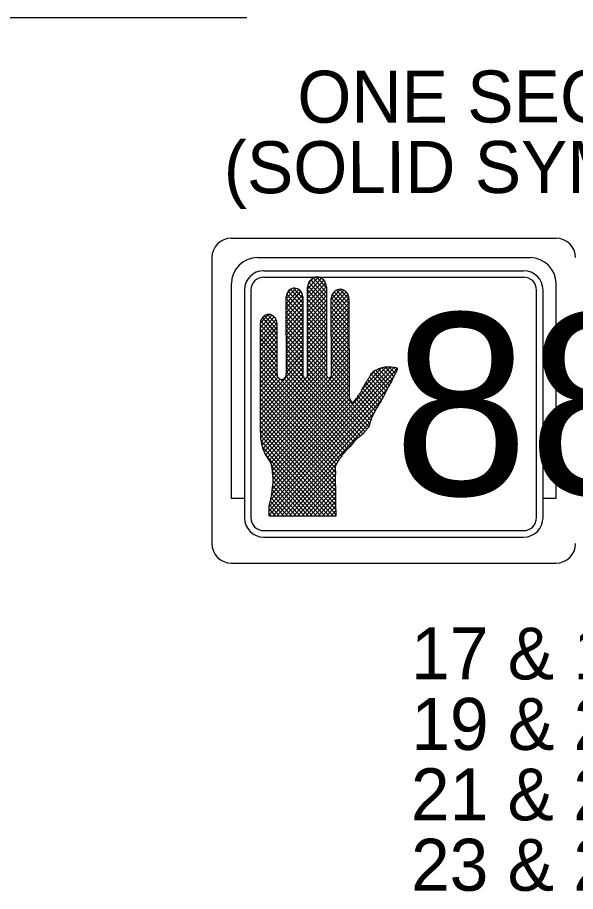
# Model space of a CAD drawing. Extents: x -19.5 to 29.5, y 0.4 to 10.6.
# Drawn here: x 4.931 to 5.647, y 9.087 to 10.208 of the extents above; entities that cross this region are included whole.
import ezdxf

# ---------------------------------------------------------------- set-up
doc = ezdxf.new("R2010")
doc.units = 0
doc.layers.add('T_Drafting', color=7, linetype='Continuous')
doc.layers.add('T_Notes', color=7, linetype='Continuous')

msp = doc.modelspace()

# ---------------------------------------------------------------- linework, layer by layer
at = {"layer": 'T_Drafting'}
for p, q in [((5.205, 9.9248), (5.6217, 9.9248)), ((5.18, 9.8998), (5.18, 9.5331)), ((5.2384, 9.8998), (5.5884, 9.8998)), ((5.2467, 9.8831), (5.58, 9.8831)), ((5.2467, 9.8748), (5.58, 9.8748)), ((5.3028, 9.8595), (5.3165, 9.8748)), ((5.3146, 9.8748), (5.3271, 9.8609)), ((5.205, 9.8665), (5.205, 9.5915)), ((5.3028, 9.8536), (5.3205, 9.8734)), ((5.3028, 9.8478), (5.3236, 9.8709)), ((5.3028, 9.8419), (5.3258, 9.8675)), ((5.3028, 9.836), (5.3271, 9.863)), ((5.303, 9.8641), (5.3272, 9.8373)), ((5.3037, 9.8664), (5.3103, 9.8738)), ((5.3045, 9.8683), (5.3272, 9.8432)), ((5.3069, 9.8715), (5.3272, 9.8491)), ((5.3102, 9.8738), (5.3272, 9.855)), ((5.3223, 9.8721), (5.3247, 9.8695)), ((5.6217, 9.5915), (5.6217, 9.8665)), ((5.2217, 9.8581), (5.2217, 9.5665)), ((5.23, 9.8581), (5.23, 9.5665)), ((5.2755, 9.8469), (5.2877, 9.8605)), ((5.2755, 9.841), (5.2916, 9.8589)), ((5.2755, 9.8351), (5.2944, 9.8562)), ((5.2755, 9.8292), (5.2962, 9.8523)), ((5.276, 9.8528), (5.2967, 9.8299)), ((5.2764, 9.8538), (5.2816, 9.8596)), ((5.278, 9.8566), (5.2967, 9.8358)), ((5.2809, 9.8592), (5.2967, 9.8417)), ((5.2849, 9.8606), (5.2967, 9.8476)), ((5.292, 9.8586), (5.2948, 9.8555)), ((5.3029, 9.7481), (5.3028, 9.8619)), ((5.3028, 9.8585), (5.3272, 9.8314)), ((5.3028, 9.8301), (5.3272, 9.8572)), ((5.3028, 9.8526), (5.3272, 9.8255)), ((5.3271, 9.8622), (5.3273, 9.7493)), ((5.3333, 9.8463), (5.345, 9.8594)), ((5.3333, 9.8404), (5.3493, 9.8582)), ((5.3333, 9.8345), (5.3525, 9.8558)), ((5.3333, 9.8286), (5.3547, 9.8525)), ((5.3345, 9.8527), (5.356, 9.8288)), ((5.3368, 9.856), (5.356, 9.8347)), ((5.34, 9.8583), (5.356, 9.8406)), ((5.3444, 9.8594), (5.3559, 9.8465)), ((5.5967, 9.5665), (5.5967, 9.8581)), ((5.605, 9.5665), (5.605, 9.8581)), ((5.2756, 9.7503), (5.2755, 9.8497)), ((5.2755, 9.8476), (5.2967, 9.824)), ((5.2755, 9.8233), (5.2967, 9.8469)), ((5.2755, 9.8417), (5.2967, 9.8181)), ((5.2755, 9.8174), (5.2967, 9.841)), ((5.2967, 9.8494), (5.2968, 9.7487)), ((5.3028, 9.8242), (5.3272, 9.8513)), ((5.3028, 9.8467), (5.3272, 9.8196)), ((5.3028, 9.8183), (5.3272, 9.8454)), ((5.3028, 9.8408), (5.3272, 9.8137)), ((5.3333, 9.8482), (5.356, 9.8229)), ((5.3334, 9.7487), (5.3333, 9.8479)), ((5.3333, 9.8227), (5.3559, 9.8479)), ((5.3333, 9.8423), (5.356, 9.817)), ((5.3333, 9.8169), (5.356, 9.842)), ((5.3559, 9.8471), (5.3561, 9.7194)), ((5.2755, 9.8358), (5.2967, 9.8122)), ((5.2755, 9.8116), (5.2967, 9.8351)), ((5.2755, 9.8299), (5.2967, 9.8063)), ((5.2755, 9.8057), (5.2967, 9.8292)), ((5.3028, 9.8125), (5.3272, 9.8395)), ((5.3028, 9.8349), (5.3272, 9.8078)), ((5.3028, 9.8066), (5.3272, 9.8336)), ((5.3333, 9.8364), (5.356, 9.8111)), ((5.3333, 9.811), (5.356, 9.8361)), ((5.3333, 9.8305), (5.356, 9.8052)), ((5.3333, 9.8051), (5.356, 9.8303)), ((5.2423, 9.8159), (5.2522, 9.827)), ((5.2423, 9.8101), (5.2568, 9.8262)), ((5.2423, 9.8042), (5.2601, 9.8239)), ((5.2423, 9.7983), (5.2624, 9.8206)), ((5.2429, 9.819), (5.2636, 9.796)), ((5.2448, 9.8228), (5.2636, 9.8019)), ((5.2477, 9.8254), (5.2635, 9.8078)), ((5.2516, 9.8269), (5.2635, 9.8137)), ((5.2584, 9.8253), (5.2621, 9.8212)), ((5.2755, 9.824), (5.2967, 9.8004)), ((5.2755, 9.7998), (5.2967, 9.8233)), ((5.2755, 9.8181), (5.2967, 9.7945)), ((5.3028, 9.829), (5.3272, 9.8019)), ((5.3028, 9.8007), (5.3272, 9.8277)), ((5.3028, 9.8231), (5.3272, 9.796)), ((5.3028, 9.7948), (5.3272, 9.8219)), ((5.3333, 9.8246), (5.356, 9.7994)), ((5.3333, 9.7992), (5.356, 9.8244)), ((5.3333, 9.8187), (5.356, 9.7935)), ((5.3333, 9.7933), (5.356, 9.8185)), ((5.2425, 9.6786), (5.2423, 9.816)), ((5.2423, 9.7924), (5.2635, 9.8159)), ((5.2423, 9.8137), (5.2636, 9.7901)), ((5.2423, 9.8078), (5.2636, 9.7842)), ((5.2424, 9.7865), (5.2635, 9.8101)), ((5.2635, 9.8158), (5.2636, 9.7502)), ((5.2755, 9.7939), (5.2967, 9.8175)), ((5.2755, 9.8122), (5.2967, 9.7886)), ((5.2755, 9.788), (5.2967, 9.8116)), ((5.3028, 9.8172), (5.3272, 9.7901)), ((5.3028, 9.7889), (5.3272, 9.816)), ((5.3028, 9.8113), (5.3272, 9.7842)), ((5.3028, 9.783), (5.3272, 9.8101)), ((5.3333, 9.8128), (5.356, 9.7876)), ((5.3333, 9.7874), (5.356, 9.8126)), ((5.3333, 9.8069), (5.356, 9.7817)), ((5.3333, 9.7816), (5.356, 9.8067)), ((5.2423, 9.8019), (5.2636, 9.7783)), ((5.2423, 9.796), (5.2636, 9.7724)), ((5.2424, 9.7806), (5.2636, 9.8042)), ((5.2424, 9.7748), (5.2636, 9.7983)), ((5.2755, 9.8063), (5.2967, 9.7827)), ((5.2755, 9.7821), (5.2967, 9.8057)), ((5.2755, 9.8004), (5.2968, 9.7768)), ((5.2755, 9.7763), (5.2967, 9.7998)), ((5.3028, 9.8054), (5.3272, 9.7783)), ((5.3028, 9.7995), (5.3272, 9.7724)), ((5.3029, 9.7771), (5.3272, 9.8042)), ((5.3029, 9.7713), (5.3272, 9.7983)), ((5.3333, 9.801), (5.356, 9.7758)), ((5.3333, 9.7757), (5.356, 9.8008)), ((5.2423, 9.7901), (5.2636, 9.7665)), ((5.2424, 9.7689), (5.2636, 9.7924)), ((5.2424, 9.763), (5.2636, 9.7865)), ((5.2755, 9.7945), (5.2968, 9.7709)), ((5.2755, 9.7704), (5.2967, 9.7939)), ((5.2755, 9.7886), (5.2968, 9.765)), ((5.2755, 9.7645), (5.2967, 9.788)), ((5.3028, 9.7936), (5.3273, 9.7665)), ((5.3028, 9.7877), (5.3273, 9.7606)), ((5.3029, 9.7654), (5.3272, 9.7924)), ((5.3029, 9.7595), (5.3272, 9.7866)), ((5.3333, 9.7951), (5.356, 9.7699)), ((5.3333, 9.7698), (5.356, 9.7949)), ((5.3333, 9.7892), (5.356, 9.764)), ((5.3334, 9.7639), (5.356, 9.7891)), ((5.2424, 9.7842), (5.2636, 9.7606)), ((5.2424, 9.7571), (5.2636, 9.7806)), ((5.2424, 9.7783), (5.2636, 9.7547)), ((5.2424, 9.7512), (5.2636, 9.7748)), ((5.2755, 9.7827), (5.2968, 9.7591)), ((5.2755, 9.7768), (5.2968, 9.7532)), ((5.2756, 9.7586), (5.2967, 9.7821)), ((5.2756, 9.7527), (5.2968, 9.7763)), ((5.3028, 9.7818), (5.3273, 9.7547)), ((5.3028, 9.7476), (5.3272, 9.7748)), ((5.3029, 9.7536), (5.3272, 9.7807)), ((5.3029, 9.7759), (5.3272, 9.7489)), ((5.3333, 9.7833), (5.356, 9.7581)), ((5.3333, 9.7774), (5.356, 9.7522)), ((5.3334, 9.758), (5.356, 9.7832)), ((5.3334, 9.7521), (5.356, 9.7773)), ((5.2424, 9.7724), (5.2638, 9.7486)), ((5.2424, 9.71), (5.2968, 9.7704)), ((5.2424, 9.7453), (5.2636, 9.7689)), ((5.2424, 9.7665), (5.3487, 9.6484)), ((5.2424, 9.7041), (5.2968, 9.7645)), ((5.2424, 9.7394), (5.2636, 9.763)), ((5.2427, 9.6749), (5.3273, 9.7689)), ((5.2429, 9.6692), (5.3273, 9.763)), ((5.2473, 9.6507), (5.356, 9.7714)), ((5.2494, 9.647), (5.356, 9.7655)), ((5.2755, 9.7709), (5.297, 9.747)), ((5.2755, 9.765), (5.3647, 9.666)), ((5.3029, 9.77), (5.3811, 9.6831)), ((5.3029, 9.7641), (5.3788, 9.6798)), ((5.3333, 9.7715), (5.356, 9.7463)), ((5.3334, 9.7656), (5.3561, 9.7404)), ((5.2424, 9.7606), (5.3462, 9.6452)), ((5.2424, 9.6982), (5.2968, 9.7586)), ((5.2424, 9.7336), (5.2636, 9.7571)), ((5.2424, 9.7547), (5.344, 9.6418)), ((5.2424, 9.7277), (5.2636, 9.7512)), ((5.2425, 9.6924), (5.2968, 9.7527)), ((5.2437, 9.6642), (5.3273, 9.7571)), ((5.2445, 9.6593), (5.3273, 9.7512)), ((5.2515, 9.6435), (5.356, 9.7596)), ((5.2536, 9.6399), (5.356, 9.7537)), ((5.2537, 9.5753), (5.4178, 9.7576)), ((5.2539, 9.5813), (5.414, 9.7592)), ((5.2557, 9.5892), (5.4092, 9.7597)), ((5.2568, 9.5964), (5.4039, 9.7597)), ((5.2756, 9.7591), (5.362, 9.663)), ((5.2756, 9.7532), (5.3594, 9.66)), ((5.3029, 9.7582), (5.3763, 9.6767)), ((5.3029, 9.7523), (5.3737, 9.6737)), ((5.3334, 9.7597), (5.3561, 9.7345)), ((5.3334, 9.7538), (5.3561, 9.7286)), ((5.3734, 9.7318), (5.3976, 9.7587)), ((5.3834, 9.7488), (5.3891, 9.7551)), ((5.3868, 9.7533), (5.4054, 9.7326)), ((5.3901, 9.7555), (5.4075, 9.7362)), ((5.3939, 9.7573), (5.4096, 9.7398)), ((5.3978, 9.7588), (5.4117, 9.7434)), ((5.4022, 9.7597), (5.4133, 9.7474)), ((5.4075, 9.7598), (5.4152, 9.7512)), ((5.4132, 9.7593), (5.4171, 9.755)), ((5.2424, 9.7488), (5.3416, 9.6386)), ((5.2424, 9.7218), (5.2647, 9.7465)), ((5.2424, 9.7159), (5.2677, 9.744)), ((5.2424, 9.7429), (5.3397, 9.6348)), ((5.2425, 9.6865), (5.297, 9.7471)), ((5.2425, 9.6806), (5.3005, 9.7451)), ((5.2456, 9.6546), (5.3282, 9.7464)), ((5.2537, 9.5694), (5.4127, 9.746)), ((5.2556, 9.6362), (5.356, 9.7479)), ((5.2571, 9.6321), (5.3561, 9.742)), ((5.2681, 9.7438), (5.3513, 9.6513)), ((5.2727, 9.7446), (5.354, 9.6542)), ((5.2751, 9.7478), (5.3567, 9.6571)), ((5.2986, 9.7453), (5.3675, 9.6687)), ((5.3025, 9.7468), (5.3706, 9.6711)), ((5.3302, 9.7456), (5.3827, 9.6872)), ((5.3333, 9.748), (5.3561, 9.7227)), ((5.3778, 9.7398), (5.3978, 9.7176)), ((5.3801, 9.7431), (5.3998, 9.7213)), ((5.3821, 9.7467), (5.4017, 9.725)), ((5.3843, 9.7502), (5.4036, 9.7288)), ((5.2424, 9.737), (5.3383, 9.6304)), ((5.2424, 9.7311), (5.3385, 9.6243)), ((5.2577, 9.6268), (5.3561, 9.7361)), ((5.2582, 9.5684), (5.4048, 9.7313)), ((5.2582, 9.6215), (5.3561, 9.7302)), ((5.372, 9.7286), (5.3914, 9.707)), ((5.3737, 9.7325), (5.3936, 9.7104)), ((5.3757, 9.7362), (5.3957, 9.7139)), ((5.2424, 9.7252), (5.3383, 9.6187)), ((5.2424, 9.7193), (5.3383, 9.6128)), ((5.2585, 9.61), (5.3568, 9.7193)), ((5.2586, 9.616), (5.3561, 9.7243)), ((5.2635, 9.5684), (5.3978, 9.7177)), ((5.365, 9.7187), (5.3856, 9.6958)), ((5.3674, 9.7218), (5.3874, 9.6997)), ((5.3697, 9.7252), (5.3894, 9.7033)), ((5.2424, 9.7134), (5.3385, 9.6066)), ((5.2424, 9.7075), (5.3386, 9.6007)), ((5.2576, 9.6031), (5.3588, 9.7155)), ((5.3625, 9.7155), (5.384, 9.6916)), ((5.2424, 9.7016), (5.3386, 9.5948)), ((5.2424, 9.6957), (5.3386, 9.5889)), ((5.2688, 9.5684), (5.3881, 9.701)), ((5.2425, 9.6898), (5.3386, 9.583)), ((5.2425, 9.6839), (5.3389, 9.5768)), ((5.2741, 9.5684), (5.3834, 9.6899)), ((5.2425, 9.678), (5.3392, 9.5705)), ((5.2427, 9.6718), (5.3357, 9.5685)), ((5.2435, 9.665), (5.3304, 9.5685)), ((5.2447, 9.6578), (5.3251, 9.5685)), ((5.2499, 9.6461), (5.3198, 9.5685)), ((5.2571, 9.6323), (5.3145, 9.5685)), ((5.2794, 9.5684), (5.3406, 9.6364)), ((5.2847, 9.5684), (5.3384, 9.6281)), ((5.2579, 9.6255), (5.3092, 9.5685)), ((5.2584, 9.6191), (5.3039, 9.5684)), ((5.29, 9.5684), (5.3384, 9.6222)), ((5.2953, 9.5684), (5.3382, 9.6161)), ((5.2583, 9.6074), (5.2934, 9.5684)), ((5.2586, 9.6129), (5.2987, 9.5684)), ((5.3006, 9.5684), (5.3384, 9.6104)), ((5.2569, 9.5971), (5.2828, 9.5684)), ((5.2575, 9.6024), (5.2881, 9.5684)), ((5.3059, 9.5684), (5.3386, 9.6047)), ((5.3113, 9.5685), (5.3386, 9.5988)), ((5.205, 9.5915), (5.2217, 9.5915)), ((5.254, 9.5827), (5.2669, 9.5684)), ((5.2551, 9.5874), (5.2722, 9.5684)), ((5.2563, 9.5919), (5.2775, 9.5684)), ((5.3166, 9.5685), (5.3386, 9.5929)), ((5.3219, 9.5685), (5.3386, 9.587)), ((5.605, 9.5915), (5.6217, 9.5915)), ((5.2538, 9.5771), (5.2616, 9.5684)), ((5.3272, 9.5685), (5.3387, 9.5812)), ((5.3325, 9.5685), (5.3389, 9.5756)), ((5.2537, 9.5712), (5.2563, 9.5684)), ((5.2542, 9.5684), (5.2537, 9.5689)), ((5.3388, 9.5685), (5.2542, 9.5684)), ((5.3378, 9.5685), (5.3392, 9.57)), ((5.3392, 9.5684), (5.3388, 9.5685)), ((5.2467, 9.5498), (5.58, 9.5498)), ((5.2467, 9.5415), (5.58, 9.5415)), ((5.205, 9.5081), (5.6217, 9.5081))]:
    msp.add_line(p, q, dxfattribs=at)
for centre, radius, start, end in [((5.205, 9.8998), 0.025, 90, 180), ((5.6217, 9.8998), 0.025, 0, 90), ((5.2384, 9.8665), 0.0333, 90, 180), ((5.5884, 9.8665), 0.0333, 0, 90), ((5.2467, 9.8581), 0.025, 90, 180), ((5.2467, 9.8581), 0.0167, 90, 180), ((5.58, 9.8581), 0.025, 0, 90), ((5.58, 9.8581), 0.0167, 0, 90), ((5.2467, 9.5665), 0.025, 180, 270), ((5.2467, 9.5665), 0.0167, 180, 270), ((5.58, 9.5665), 0.025, 270, 0), ((5.58, 9.5665), 0.0167, 270, 0), ((5.205, 9.5331), 0.025, 180, 270), ((5.6217, 9.5331), 0.025, 270, 0)]:
    msp.add_arc(centre, radius, start, end, dxfattribs=at)
for centre, major_axis, start_param, end_param in [((5.315, 9.8613), (0, -0.0136), 1.640121, 4.665593), ((5.2861, 9.8489), (0, -0.0118), 1.618611, 4.644084), ((5.3446, 9.8467), (0, -0.0126), 1.597842, 4.623315), ((5.2529, 9.8152), (0, -0.0118), 1.618611, 4.644084), ((5.2696, 9.7502), (0, -0.00664), 4.713646, 7.855239), ((5.2998, 9.7484), (0, -0.0034), 4.633755, 7.775348), ((5.3303, 9.749), (0, -0.00345), 4.624552, 7.766145)]:
    msp.add_ellipse(centre, major_axis=major_axis, ratio=0.9, start_param=start_param, end_param=end_param, dxfattribs=at)
for points in [[(5.3561, 9.7195), (5.3569, 9.7192), (5.3581, 9.7167), (5.3596, 9.7147), (5.3604, 9.7144), (5.3619, 9.7147), (5.3628, 9.716), (5.3654, 9.7192), (5.3675, 9.7219), (5.3686, 9.7238), (5.3698, 9.7255), (5.3719, 9.7284), (5.373, 9.731), (5.3748, 9.7346), (5.376, 9.7365), (5.378, 9.7401), (5.3803, 9.7434), (5.3821, 9.7467), (5.3841, 9.7499), (5.3859, 9.7522), (5.3885, 9.7548), (5.3917, 9.7561), (5.3935, 9.7571), (5.3962, 9.7581), (5.3985, 9.7591), (5.402, 9.7597), (5.405, 9.7598), (5.4088, 9.7598), (5.4123, 9.7594), (5.4164, 9.7588), (5.4176, 9.7581), (5.4178, 9.7572), (5.4161, 9.7529), (5.4149, 9.7506), (5.4138, 9.7483), (5.4126, 9.7457), (5.412, 9.7441), (5.4097, 9.7398), (5.4062, 9.734), (5.4015, 9.7245), (5.3956, 9.7137), (5.391, 9.7062), (5.3883, 9.7013), (5.386, 9.6968), (5.3846, 9.6931), (5.3839, 9.6913), (5.3813, 9.6834), (5.3772, 9.6779), (5.374, 9.674), (5.3693, 9.67), (5.3663, 9.6677), (5.3587, 9.6592), (5.352, 9.6521), (5.3476, 9.6472), (5.3438, 9.6416), (5.3419, 9.6392), (5.3403, 9.6358), (5.3385, 9.6325), (5.3385, 9.6253), (5.3383, 9.6189), (5.3383, 9.613), (5.3386, 9.6052), (5.3386, 9.5977), (5.3386, 9.5856), (5.3389, 9.5759), (5.3392, 9.5723), (5.3392, 9.5697), (5.3392, 9.5684)], [(5.2537, 9.5689), (5.2537, 9.5741), (5.254, 9.5829), (5.2563, 9.5921), (5.2575, 9.6025), (5.2584, 9.6084), (5.2584, 9.6198), (5.2575, 9.6292), (5.2566, 9.6341), (5.2522, 9.6423), (5.2475, 9.6504), (5.2448, 9.6573), (5.2436, 9.6644), (5.2427, 9.67), (5.2427, 9.6735), (5.2425, 9.6786)]]:
    msp.add_spline(points, degree=3, dxfattribs=at)
at = {"layer": 'T_Notes'}
msp.add_line((3.5887, 10.2078), (5.2251, 10.2078), dxfattribs=at)

# ---------------------------------------------------------------- texts
at = {"layer": 'T_Drafting'}
for s, height, p in [('ONE SECTION', 0.066667, (5.2898, 10.0728)), ('(SOLID SYMBOL)', 0.066667, (5.1954, 9.9823)), ('88', 0.23333, (5.4128, 9.5952))]:
    msp.add_text(s, height=height, rotation=0.072, dxfattribs=at).set_placement(p)
at = {"layer": 'T_Notes'}
for s, p in [('17 & 18', (5.4357, 9.359)), ('19 & 20', (5.436, 9.2686)), ('21 & 22', (5.4355, 9.1783)), ('23 & 24', (5.4356, 9.088))]:
    msp.add_text(s, height=0.06667, dxfattribs=at).set_placement(p)

doc.saveas('drawing.dxf')
